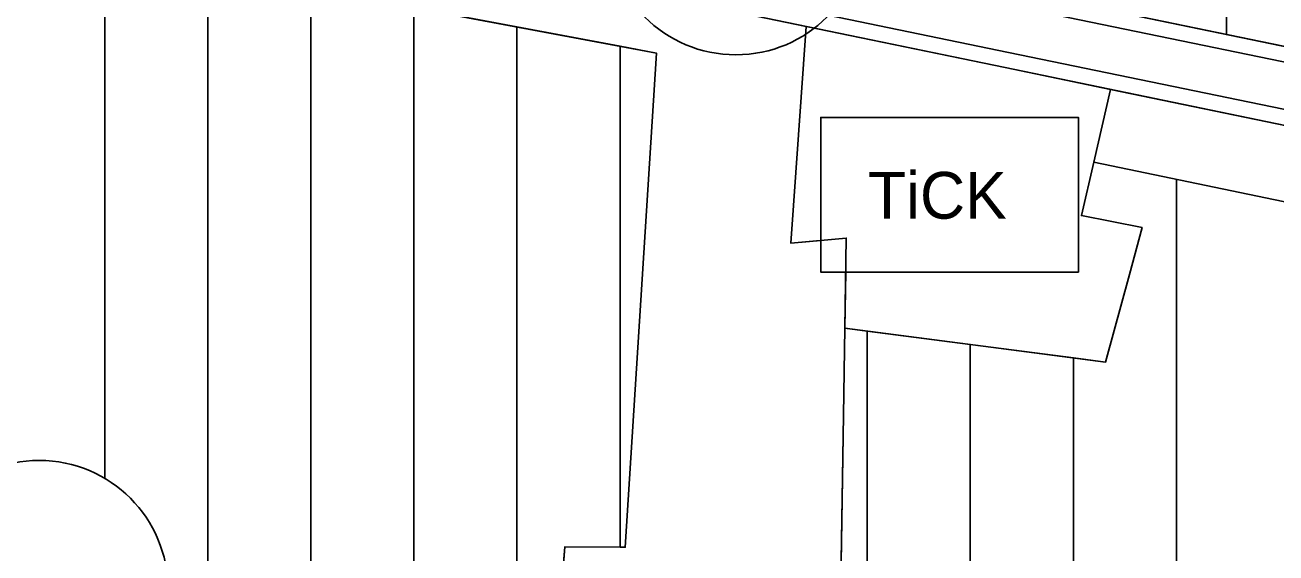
# Model space of a CAD drawing. Extents: x 427903 to 430077, y 4477233 to 4480385.
# Drawn here: x 428734.8 to 428977.5, y 4477497.4 to 4477599.8 of the extents above; entities that cross this region are included whole.
import ezdxf

# ---------------------------------------------------------------- set-up
doc = ezdxf.new("R2010")
doc.units = 0
for name, color, linetype in [('ADAKENARI', 7, 'Continuous'), ('KALDIRIM', 7, 'Continuous'), ('KD_KAV_DA', 7, 'Continuous'), ('LJ_SEMBOL', 7, 'Continuous'), ('PL_K_TALI_IS_MRK', 7, 'Continuous'), ('PL_KON_MEV_150', 7, 'Continuous'), ('PL_TİC+K', 7, 'Continuous'), ('SM_DAIRE', 7, 'Continuous'), ('TR_AZYOGUNKONUT', 7, 'Continuous'), ('TR_TALIISMERK', 7, 'Continuous'), ('TR_TİC+K', 7, 'Continuous')]:
    doc.layers.add(name, color=color, linetype=linetype)

msp = doc.modelspace()

# ---------------------------------------------------------------- linework, layer by layer
at = {"layer": 'ADAKENARI'}
for p, q in [((428615.63, 4477655.53), (428924.99, 4477591.56)), ((428857.27, 4477594.38), (428605.75, 4477641.43)), ((429055.28, 4477579.93), (428907.79, 4477610.43)), ((428851.24, 4477498.49), (428857.27, 4477594.38)), ((428924.99, 4477591.56), (429052.27, 4477565.24)), ((428892.66, 4477466.82), (428893.57, 4477524.11)), ((428838.69, 4477488.35), (428839.52, 4477498.6)), ((428839.52, 4477498.6), (428851.24, 4477498.49))]:
    msp.add_line(p, q, dxfattribs=at)
at = {"layer": 'KALDIRIM'}
for p, q in [((428633.12, 4477654.98), (428925.59, 4477594.5)), ((428907.19, 4477607.49), (429054.67, 4477577)), ((428925.59, 4477594.5), (429052.87, 4477568.18))]:
    msp.add_line(p, q, dxfattribs=at)
at = {"layer": 'KD_KAV_DA'}
msp.add_circle((428872.71, 4477619.03), 25, dxfattribs=at)
at = {"layer": 'LJ_SEMBOL'}
msp.add_lwpolyline([(428889.17, 4477581.89), (428939.17, 4477581.89), (428939.17, 4477551.89), (428889.17, 4477551.89), (428889.17, 4477581.89), (428939.17, 4477581.89)], dxfattribs=at)
at = {"layer": 'PL_K_TALI_IS_MRK'}
for points in [[(429055.28, 4477579.93), (428907.79, 4477610.43), (428904.67, 4477611.29), (428901.68, 4477612.55), (428898.88, 4477614.19), (428896.31, 4477616.17), (428894.03, 4477618.47), (428892.06, 4477621.04), (428890.44, 4477623.85), (428889.19, 4477626.85), (428888.35, 4477629.98), (428887.92, 4477633.19), (428887.9, 4477636.44), (428888.31, 4477639.65), (428914.9, 4477777.38), (428919.56, 4477811.73), (428920.55, 4477818.42), (428921.68, 4477825.08), (428922.96, 4477831.72), (428924.39, 4477838.32), (428925.97, 4477844.9), (428927.69, 4477851.43), (428927.69, 4477851.43), (429143.97, 4477860.98)], [(428891.92, 4477420.61), (428878.39, 4477421.75), (428877.77, 4477465.86), (428888.48, 4477466.51), (428892.66, 4477466.82), (428893.57, 4477524.11), (428893.84, 4477540.99), (428894.12, 4477558.47), (428883.39, 4477557.49), (428886.38, 4477599.54), (428621.21, 4477654.38), (428621.21, 4477654.38), (428615.63, 4477655.53), (428463.01, 4477687.09)], [(428690.22, 4477625.63), (428710.22, 4477621.89), (428730.22, 4477618.14), (428750.22, 4477614.4), (428770.22, 4477610.66), (428790.22, 4477606.92), (428810.22, 4477603.18), (428830.22, 4477599.44), (428850.22, 4477595.7), (428857.27, 4477594.38), (428851.24, 4477498.49), (428850.22, 4477498.5), (428839.52, 4477498.6), (428838.69, 4477488.35)], [(429194.39, 4477536.36), (429052.27, 4477565.24), (428945.43, 4477587.33), (428942.16, 4477573.18), (428978.93, 4477565.57), (429016.97, 4477557.7)]]:
    msp.add_lwpolyline(points, dxfattribs=at)
at = {"layer": 'PL_KON_MEV_150'}
msp.add_lwpolyline([(428857.27, 4477594.38), (428851.24, 4477498.49), (428839.52, 4477498.6), (428838.69, 4477488.35), (428855.47, 4477480.87), (428852.32, 4477379.82), (428847.13, 4477374.01), (428765.15, 4477379.18), (428757.18, 4477388.77), (428744.71, 4477386.69), (428724.03, 4477368.58), (428691.7, 4477357.89), (428668.48, 4477380.82), (428635.65, 4477394.31), (428637.38, 4477422.86), (428644.03, 4477428.66), (428637.63, 4477449.23), (428630.48, 4477467.61), (428633.92, 4477521.77), (428634.94, 4477552.53), (428603.35, 4477620.21), (428605.75, 4477641.43)], close=True, dxfattribs=at)
msp.add_lwpolyline([(428978.93, 4477565.57), (428942.16, 4477573.18), (428939.78, 4477562.84), (428951.55, 4477560.51), (428949.08, 4477551.4), (428944.47, 4477534.41), (428920.67, 4477537.51), (428893.84, 4477540.99), (428893.57, 4477524.11), (428892.66, 4477466.82), (428895.41, 4477467.03), (428897.05, 4477467.09), (428900.98, 4477467.01), (428902.48, 4477467.49), (428909.75, 4477469.83), (428916.82, 4477472.17), (428928.93, 4477471.8), (428914.53, 4477418.72), (428891.92, 4477420.61), (428891, 4477363.21)], dxfattribs=at)
at = {"layer": 'PL_TİC+K'}
msp.add_lwpolyline([(428945.43, 4477587.33), (428924.99, 4477591.56), (428886.38, 4477599.54), (428883.39, 4477557.49), (428894.12, 4477558.47), (428893.84, 4477540.99), (428898.2, 4477540.42), (428918.2, 4477537.83), (428920.67, 4477537.51), (428938.2, 4477535.23), (428944.47, 4477534.41), (428949.08, 4477551.4), (428951.55, 4477560.51), (428939.78, 4477562.84), (428942.16, 4477573.18), (428945.43, 4477587.33)], dxfattribs=at)
at = {"layer": 'SM_DAIRE'}
msp.add_circle((428737.52, 4477490.34), 25, dxfattribs=at)
at = {"layer": 'TR_AZYOGUNKONUT'}
for p, q in [((428750.22, 4477511.88), (428750.22, 4477614.4)), ((428770.22, 4477378.86), (428770.22, 4477610.66)), ((428790.22, 4477377.6), (428790.22, 4477606.92)), ((428810.22, 4477376.34), (428810.22, 4477603.18)), ((428830.22, 4477375.08), (428830.22, 4477599.44)), ((428850.22, 4477498.5), (428850.22, 4477595.7)), ((428958.2, 4477455.29), (428958.2, 4477569.86)), ((428898.2, 4477467.07), (428898.2, 4477540.42)), ((428918.2, 4477472.13), (428918.2, 4477537.83)), ((428938.2, 4477449.52), (428938.2, 4477535.23))]:
    msp.add_line(p, q, dxfattribs=at)
for points in [[(428691.7, 4477357.89), (428724.03, 4477368.58), (428744.71, 4477386.69), (428757.18, 4477388.77), (428765.15, 4477379.18), (428847.13, 4477374.01), (428852.32, 4477379.82), (428855.47, 4477480.87), (428838.69, 4477488.35), (428839.52, 4477498.6), (428851.24, 4477498.49), (428857.27, 4477594.38), (428605.75, 4477641.43), (428603.35, 4477620.21), (428634.94, 4477552.53), (428633.92, 4477521.77), (428630.48, 4477467.61), (428637.63, 4477449.23), (428644.03, 4477428.66), (428637.38, 4477422.86), (428635.65, 4477394.31), (428668.48, 4477380.82), (428691.7, 4477357.89)], [(429204.39, 4477518.91), (428978.93, 4477565.57), (428942.16, 4477573.18), (428939.78, 4477562.84), (428951.55, 4477560.51), (428949.08, 4477551.4), (428944.47, 4477534.41), (428920.67, 4477537.5), (428893.84, 4477540.99), (428893.57, 4477524.11), (428892.66, 4477466.82)]]:
    msp.add_lwpolyline(points, dxfattribs=at)
at = {"layer": 'TR_TALIISMERK'}
msp.add_line((428967.9, 4477598), (428967.9, 4477614.25), dxfattribs=at)
for points in [[(428891.92, 4477420.61), (428878.39, 4477421.75), (428877.77, 4477465.86), (428888.48, 4477466.51), (428892.66, 4477466.82), (428893.57, 4477524.11), (428893.84, 4477540.99), (428894.12, 4477558.47), (428883.39, 4477557.49), (428886.38, 4477599.54), (428621.21, 4477654.38), (428621.21, 4477654.38), (428615.63, 4477655.53), (428463.01, 4477687.09)], [(428730.22, 4477618.14), (428750.22, 4477614.4), (428770.22, 4477610.66), (428790.22, 4477606.92), (428810.22, 4477603.18), (428830.22, 4477599.44), (428850.22, 4477595.7), (428857.27, 4477594.38), (428851.24, 4477498.49), (428850.22, 4477498.5), (428839.52, 4477498.6), (428838.69, 4477488.35)], [(429194.39, 4477536.36), (429052.27, 4477565.24), (428945.43, 4477587.33), (428942.16, 4477573.18), (428978.93, 4477565.57), (429016.97, 4477557.7)]]:
    msp.add_lwpolyline(points, dxfattribs=at)
at = {"layer": 'TR_TİC+K'}
msp.add_lwpolyline([(428889.17, 4477558.02), (428889.17, 4477581.89), (428939.17, 4477581.89), (428939.17, 4477551.89), (428894.02, 4477551.89), (428893.84, 4477540.99), (428898.2, 4477540.42), (428918.2, 4477537.83), (428920.67, 4477537.51), (428938.2, 4477535.23), (428944.47, 4477534.41), (428949.08, 4477551.4), (428951.55, 4477560.51), (428939.78, 4477562.84), (428942.16, 4477573.18), (428945.43, 4477587.33), (428924.99, 4477591.56), (428886.38, 4477599.54), (428883.39, 4477557.49), (428889.17, 4477558.02)], dxfattribs=at)

# ---------------------------------------------------------------- texts
at = {"layer": 'LJ_SEMBOL'}
msp.add_text('TiCK', height=9.07, dxfattribs=at).set_placement((428898.33, 4477562.24))

doc.saveas('drawing.dxf')
